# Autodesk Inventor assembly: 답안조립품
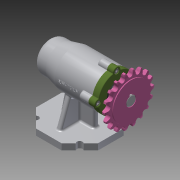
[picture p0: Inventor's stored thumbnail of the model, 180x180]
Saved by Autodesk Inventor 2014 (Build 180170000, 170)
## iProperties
Created: 2021-01
Part Number: 답안조립품
Document SubType Name: Assembly
Designer: kh
Author: kh
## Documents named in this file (12)
- C:\Users\kh\Desktop\710106V1019\답안조립품.iam
- C:\Users\kh\Desktop\710106V1019\본체.ipt
- C:\Users\kh\Desktop\710106V1019\멈춤나사 M3.ipt
- C:\Users\kh\Desktop\710106V1019\베어링 6004.ipt
- C:\Users\kh\Desktop\710106V1019\베어링 51202.ipt
- C:\Users\kh\Desktop\710106V1019\볼트 M4.ipt
- C:\Users\kh\Desktop\710106V1019\스프로킷.ipt
- C:\Users\kh\Desktop\710106V1019\어댑터슬리브.ipt
- C:\Users\kh\Desktop\710106V1019\오일 실.ipt
- C:\Users\kh\Desktop\710106V1019\축.ipt
- C:\Users\kh\Desktop\710106V1019\커버.ipt
- C:\Users\kh\Desktop\710106V1019\키 5 x 5 x 14.ipt
